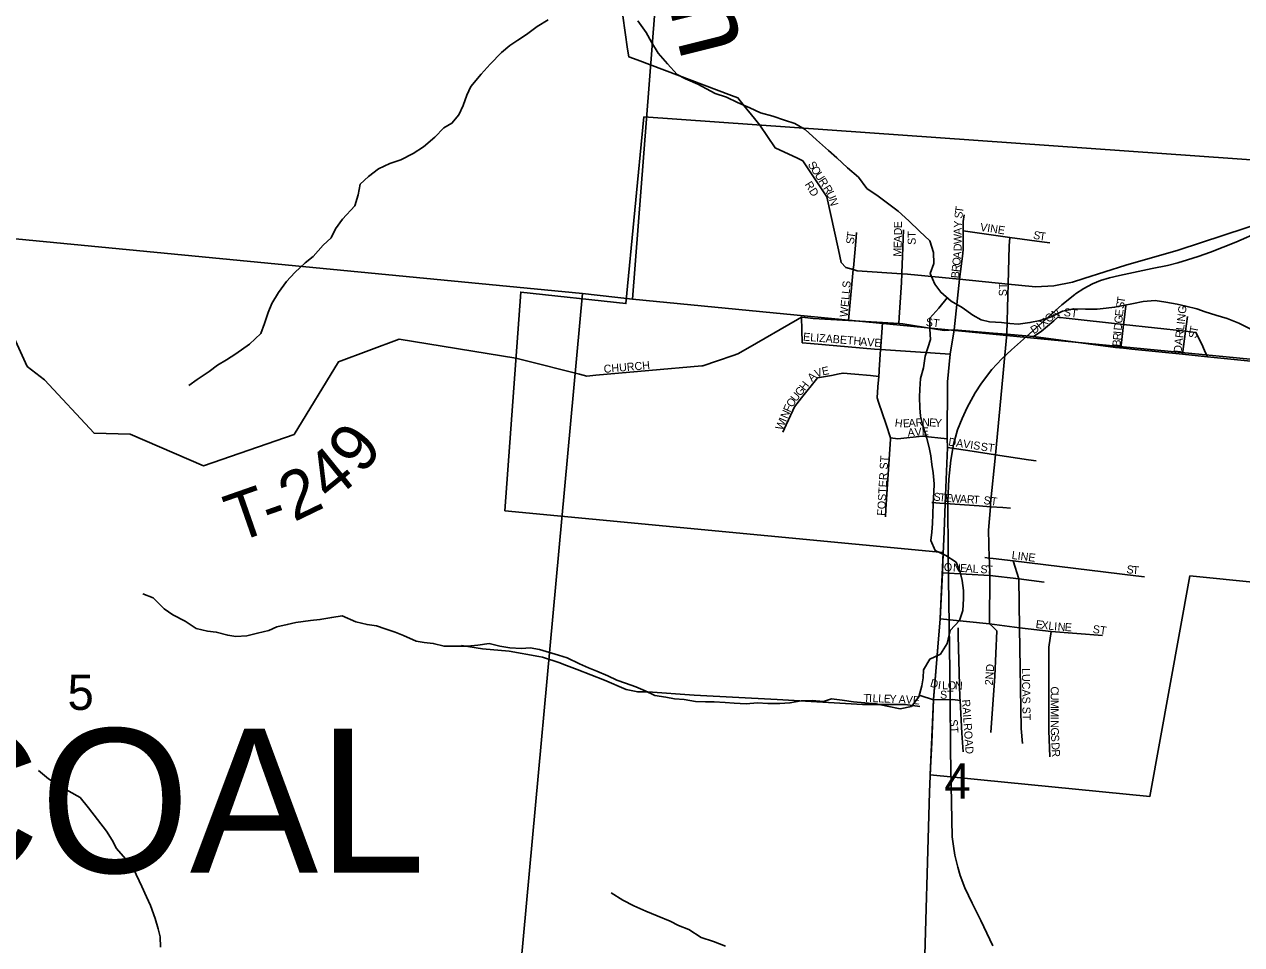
# Model space of a CAD drawing. Extents: x 1715311 to 2083412, y 146837 to 553079.
# Drawn here: x 1931050 to 1938656, y 401506 to 407256 of the extents above; entities that cross this region are included whole.
import ezdxf

# ---------------------------------------------------------------- set-up
doc = ezdxf.new("R2010")
doc.units = 0
for name, color, linetype in [('GM_X_City_Street', 7, 'Continuous'), ('GM_X_City_Street_Text', 7, 'Continuous'), ('GM_X_Corporation', 7, 'Continuous'), ('GM_X_County_Road', 7, 'Continuous'), ('GM_X_Minor_River', 7, 'Continuous'), ('GM_X_Minor_River_Text', 7, 'Continuous'), ('GM_X_Rail_Line', 7, 'Continuous'), ('GM_X_Section', 7, 'Continuous'), ('GM_X_Section_Text', 7, 'Continuous'), ('GM_X_State_Route', 7, 'Continuous'), ('GM_X_Township_Road', 7, 'Continuous'), ('GM_X_Township_Road_Text', 7, 'Continuous'), ('GM_X_Township_ROW', 7, 'Continuous'), ('GM_X_Township_Text', 7, 'Continuous')]:
    doc.layers.add(name, color=color, linetype=linetype)

msp = doc.modelspace()

# ---------------------------------------------------------------- linework, layer by layer
at = {"layer": 'GM_X_City_Street'}
for points in [[(1935880.6, 406419.3), (1935913.9, 406403.7), (1935963.9, 406329.1), (1936064.7, 406177.8), (1936138.1, 405847), (1936154.4, 405768.9), (1936183, 405736.4), (1936229.1, 405723.8), (1936253.3, 405717.1), (1936533.2, 405698), (1936567.8, 405695.6), (1936892.9, 405663.9)], [(1936913.6, 405823.7), (1936917.2, 405851.3), (1936917.1, 405965.8), (1936917, 406024.3), (1936922, 406065)], [(1936230.1, 405735.1), (1936245.4, 405898.8), (1936250.6, 405954.8)], [(1936533.5, 405706), (1936535.2, 405753.3), (1936541.2, 405918), (1936543.2, 405972.8)], [(1936917.1, 405965.8), (1936959.7, 405959.9), (1937208.5, 405925.2), (1937407.4, 405897.5), (1937457.1, 405890.6)], [(1937196.1, 405561.4), (1937197.9, 405632.9), (1937204, 405873.2), (1937208.5, 405925.2)], [(1936892.9, 405663.9), (1936913.6, 405823.7)], [(1936199.4, 405405.5), (1936203.7, 405451.5), (1936229.1, 405723.8), (1936229.8, 405731.1), (1936230.1, 405735.1)], [(1936514.1, 405386.3), (1936516.5, 405424.3), (1936530, 405643.6), (1936533.2, 405698), (1936533.5, 405706)], [(1937173.5, 405146.2), (1937190.1, 405319.9), (1937196.1, 405561.4)], [(1937919.6, 405392.4), (1937925.8, 405444.9), (1937932.1, 405497.7)], [(1934122.1, 405171.2), (1934171.8, 405158.6), (1934519.6, 405070.5), (1934565, 405058.9), (1934620.4, 405063.8), (1935284.3, 405122.6), (1935290.5, 405123), (1935381.6, 405153.9), (1935478.7, 405186.9), (1935509, 405197.2), (1935570.1, 405232.4), (1935881.1, 405411.4), (1935905.8, 405425.7), (1935926.9, 405423.7), (1935929.5, 405423.5)], [(1935911.2, 405267.1), (1935908.5, 405346.4), (1935905.8, 405425.7)], [(1935929.5, 405423.5), (1935979.5, 405418.9), (1936199.4, 405405.5), (1936412.4, 405392.5), (1936514.1, 405386.3), (1936539.9, 405384.7), (1936796.9, 405343.6)], [(1937354.8, 405305.8), (1937404, 405336.8), (1937483.4, 405403.8), (1937507.2, 405425.6), (1937516, 405424.6), (1937525.1, 405423.7)], [(1937525.1, 405423.7), (1937560.1, 405419.8), (1937918.2, 405380.8), (1938305.1, 405338.7), (1938368, 405331.8), (1938371.1, 405331.4), (1938406.6, 405257), (1938425, 405218.4), (1938443.5, 405179.6)], [(1938286.9, 405195.4), (1938292.9, 405242.6), (1938305.1, 405338.7), (1938311, 405384.4), (1938317, 405431.6)], [(1936401.9, 405245.3), (1936408, 405330.4), (1936412.4, 405392.5)], [(1936796.9, 405343.6), (1936797.7, 405343.4), (1936860.8, 405348.1), (1937103.5, 405327.3)], [(1937103.5, 405327.3), (1937190.1, 405319.9), (1937307.9, 405309.9)], [(1937900.8, 405234.3), (1937907, 405286.4), (1937918.2, 405380.8), (1937919.5, 405392.1), (1937919.6, 405392.4)], [(1935911.2, 405267.1), (1935961.4, 405262.7), (1936362.8, 405227.5), (1936400, 405224.9)], [(1937307.9, 405309.9), (1937354.8, 405305.8), (1937867.5, 405237.7), (1937892.1, 405235.2), (1937900.8, 405234.3), (1937969.4, 405227.4), (1938286.9, 405195.4), (1938443.5, 405179.6), (1938734.5, 405150.2), (1938786, 405145)], [(1936391.4, 405098.1), (1936400.4, 405224.8), (1936401, 405233.4), (1936401.9, 405245.3)], [(1936400, 405224.9), (1936400.4, 405224.8), (1936617.5, 405209.7), (1936835.1, 405195.6)], [(1936430.9, 404179), (1936434.1, 404227.5), (1936462.5, 404664.3), (1936463, 404672), (1936434.5, 404756.9), (1936388, 404895.2), (1936378.8, 404922.6), (1936383.7, 404990.8), (1936388.4, 405056.7), (1936390.6, 405087.8), (1936391.4, 405098.1)], [(1937080.4, 403902.7), (1937079.8, 403921.1), (1937073.8, 404096.6), (1937086.1, 404242.1), (1937087.9, 404263.4), (1937117.4, 404567.1), (1937164.8, 405053.9), (1937173.5, 405146.2)], [(1935789.6, 404708.1), (1935810, 404753), (1935851, 404842.8), (1935861.7, 404866.5), (1935907.2, 404923.2), (1935999.6, 405038.9), (1936006, 405046.9), (1936092.9, 405063.1), (1936141.4, 405072.3), (1936166.4, 405076.9), (1936239.4, 405070.3), (1936337.7, 405061.3), (1936388.4, 405056.7)], [(1936463, 404672), (1936509, 404667.4), (1936659.6, 404683), (1936815.8, 404667.2)], [(1936817.6, 404612.8), (1936972, 404589.9), (1937117.4, 404567.1), (1937324, 404534.6), (1937373, 404529.7)], [(1936721.3, 404268.1), (1936770.4, 404264.5), (1936803.6, 404262.2), (1937016, 404247.1), (1937016.1, 404247.1)], [(1937016.1, 404247.1), (1937086.1, 404242.1), (1937163.4, 404236.6), (1937212.6, 404233)], [(1937050.9, 403924.6), (1937079.8, 403921.1), (1937103.4, 403918.2), (1937227.8, 403903.2), (1937995.8, 403810.5), (1938048.4, 403804.1)], [(1937099, 403494), (1937081.5, 403510.7), (1937083.5, 403812.8), (1937080.4, 403902.7)], [(1937286.4, 402763.3), (1937278.2, 402857), (1937267.8, 403485.2), (1937263.9, 403791.3), (1937227.8, 403903.2)], [(1936787.3, 403828.5), (1937083.5, 403812.8), (1937263.9, 403791.3), (1937422.8, 403771.6)], [(1936771.7, 403542.1), (1937081.5, 403510.7), (1937267.8, 403485.2), (1937465.9, 403461.7), (1937787.5, 403438.1)], [(1936896.5, 403049.9), (1936884.8, 403436.3), (1936885.9, 403486.3)], [(1937089.6, 402830.8), (1937114.9, 403183.1), (1937126.6, 403467.6), (1937099, 403494)], [(1937457.1, 402679.3), (1937451.6, 402844.6), (1937451, 403364.8), (1937465.9, 403461.7)], [(1936648.3, 403062.9), (1936730.6, 403036.1), (1936852, 403037.9), (1936897, 403031.3)], [(1936915.3, 402710.8), (1936908.8, 402826.6), (1936897, 403031.3), (1936896.5, 403049.9)], [(1936288.1, 403007.6), (1936553, 403005.8), (1936644.7, 402993.6)]]:
    msp.add_lwpolyline(points, dxfattribs=at)
at = {"layer": 'GM_X_Corporation'}
msp.add_lwpolyline([(1934052.8, 404217.1), (1934152, 405583.3), (1934809.5, 405511.7), (1934921.5, 406677.6), (1939775.2, 406333.8), (1939659.7, 403677.7), (1938332.9, 403810.3), (1938081.7, 402431.6), (1936711.1, 402567.7), (1936730.7, 403037), (1936771.6, 403542.1), (1936791.1, 403956.6)], close=True, dxfattribs=at)
at = {"layer": 'GM_X_County_Road'}
msp.add_lwpolyline([(1934789.6, 407309.3), (1934819.9, 407101.9), (1934827, 407053.6), (1934879.4, 407033.9), (1935467.8, 406812.4), (1935509, 406796.9), (1935546.9, 406749.4), (1935612.3, 406667.5), (1935645.3, 406626.3), (1935741.2, 406484.3), (1935880.6, 406419.3)], dxfattribs=at)
at = {"layer": 'GM_X_Minor_River'}
for points in [[(1934324.1, 407284.8), (1934254, 407243), (1934187.9, 407193.2), (1934133.8, 407157.3), (1934083.8, 407123.5), (1934031.7, 407079.6), (1933961.5, 407007.7), (1933905.3, 406945.8), (1933841.1, 406868), (1933814.9, 406814), (1933792.7, 406748), (1933764.6, 406690), (1933722.4, 406638.1), (1933672.4, 406610.2), (1933614.2, 406550.4), (1933544.1, 406490.5), (1933480, 406448.7), (1933401.9, 406408.9), (1933333.9, 406387.1), (1933263.8, 406353.3), (1933199.7, 406305.5), (1933149.6, 406257.6), (1933135.4, 406191.6), (1933115.2, 406121.5), (1933039.2, 406039.4)], [(1934883.6, 407278.9), (1934935.3, 407204.7), (1934969.1, 407144.5), (1935010.8, 407076.3), (1935068.5, 407010), (1935130.2, 406941.7), (1935182.1, 406915.5), (1935257.9, 406883.2), (1935311.8, 406853), (1935367.6, 406824.8), (1935437.5, 406800.5), (1935507.3, 406768.2), (1935583.1, 406733.9), (1935651, 406703.7), (1935726.8, 406681.4), (1935800.7, 406657.1), (1935864.5, 406636.9), (1935928.4, 406598.6), (1936000.1, 406534.3), (1936075.8, 406468), (1936127.6, 406421.7), (1936193.3, 406359.4), (1936263, 406301.1), (1936314.8, 406230.9), (1936384.5, 406182.6), (1936444.3, 406138.3), (1936510.1, 406088.1), (1936577.8, 406027.8), (1936643.5, 405963.5), (1936707.3, 405903.2), (1936731, 405831), (1936732.8, 405762.9), (1936710.6, 405698.9), (1936738.3, 405632.8), (1936776.1, 405582.6), (1936841.9, 405526.3), (1936909.7, 405488), (1936977.5, 405439.7), (1937029.3, 405409.5), (1937081.2, 405397.3), (1937155.1, 405393.1), (1937207.1, 405386.9), (1937261, 405382.7), (1937333, 405392.5), (1937397, 405406.3), (1937467, 405428), (1937537.1, 405463.9), (1937605.1, 405479.6), (1937681, 405477.4), (1937752.9, 405477.1), (1937808.9, 405483), (1937862.9, 405488.8), (1937916.8, 405498.6), (1937980.8, 405512.4), (1938040.8, 405524.2), (1938116.8, 405530), (1938182.7, 405519.7), (1938252.6, 405507.5), (1938308.5, 405495.3), (1938376.4, 405479), (1938428.3, 405460.8), (1938494.1, 405438.6)], [(1933039.2, 406039.4), (1932993.5, 405979.5), (1932967.1, 405921.6), (1932916.9, 405875.9), (1932854.5, 405806.2), (1932804.3, 405766.5), (1932739.9, 405704.9), (1932687.6, 405649.2), (1932639.2, 405581.4), (1932596.7, 405511.6), (1932574.4, 405455.7), (1932551.9, 405387.7), (1932527.5, 405323.8), (1932457.1, 405258.2), (1932370.8, 405196.7), (1932312.6, 405161), (1932256.5, 405127.4), (1932204.2, 405087.7), (1932130, 405036.1), (1932077.8, 405000.4)], [(1936816.1, 405548.3), (1936763.8, 405482.5), (1936707.6, 405420.6), (1936707.4, 405352.5), (1936711.2, 405286.4), (1936678.8, 405182.4), (1936668.6, 405110.4), (1936650.4, 405042.4), (1936646.2, 404976.3), (1936644, 404926.2), (1936645.8, 404860.1), (1936649.6, 404808.1), (1936663.4, 404750), (1936687.1, 404677.8), (1936702.9, 404611.7), (1936714.7, 404559.6), (1936720.5, 404505.5), (1936728.3, 404453.4), (1936736.1, 404385.3), (1936733.9, 404333.2), (1936729.6, 404263.2), (1936727.4, 404195.1), (1936725.2, 404137), (1936721, 404083), (1936714.9, 404031), (1936740.6, 403968.8), (1936808.4, 403936.5), (1936872.3, 403896.3), (1936898, 403834.1), (1936909.8, 403782), (1936917.6, 403717.9), (1936919.4, 403667.8), (1936915.2, 403593.8), (1936893, 403531.8), (1936834.8, 403467.9), (1936816.6, 403387.8), (1936774.4, 403321.9), (1936708.3, 403290.1), (1936668.1, 403224.2), (1936665.9, 403174.1), (1936657.8, 403124.1), (1936639.6, 403054), (1936593.4, 402994.1), (1936523.4, 402980.4), (1936441.5, 402996.6), (1936373.6, 403010.9), (1936301.7, 403017.1), (1936231.8, 403023.4), (1936159.9, 403033.6), (1936094, 403041.9), (1936044, 403026), (1935972.1, 403032.3), (1935904.1, 403030.5), (1935834.1, 403016.7), (1935770.2, 403012.9), (1935696.2, 403013.2), (1935630.3, 403017.4), (1935560.4, 403011.6), (1935486.4, 403013.9), (1935428.5, 403020.1), (1935360.6, 403022.3), (1935306.6, 403022.5), (1935244.7, 403024.7), (1935172.8, 403037), (1935112.9, 403041.2), (1935058.9, 403051.4), (1934989, 403063.6), (1934929.2, 403091.9), (1934871.3, 403116.1), (1934807.5, 403140.3), (1934751.6, 403158.5), (1934695.7, 403184.8), (1934627.9, 403215), (1934576, 403235.2), (1934520.1, 403261.5), (1934442.3, 403297.8), (1934388.4, 403314), (1934268.6, 403350.4), (1934210.7, 403360.6), (1934156.8, 403356.8), (1934084.8, 403361), (1934020.9, 403371.3), (1933955, 403387.5), (1933883.1, 403377.7), (1933819.1, 403372), (1933745.2, 403370.2), (1933673.2, 403370.4), (1933605.4, 403388.7), (1933549.4, 403394.9), (1933497.5, 403403.1), (1933419.7, 403437.4), (1933367.8, 403457.6), (1933303.9, 403479.8), (1933250, 403498), (1933192.1, 403506.2), (1933122.2, 403522.5), (1933035.7, 403560.3)], [(1938494.1, 405438.6), (1938566, 405418.3), (1938637.8, 405390.1), (1938713.6, 405351.8)], [(1933035.7, 403560.3), (1932971, 403550.6), (1932897, 403537.1), (1932839, 403531.5), (1932747, 403518.1), (1932693, 403506.4), (1932628.9, 403492.8), (1932578.8, 403469.1), (1932506.8, 403451.6), (1932440.7, 403436), (1932372.8, 403430.5), (1932320.9, 403438.8), (1932249.1, 403459.3), (1932195.2, 403465.7), (1932123.4, 403482.2), (1932055.8, 403526.7), (1931978.1, 403567.3), (1931924.4, 403603.7), (1931855, 403672.2), (1931791.2, 403698.7)], [(1931902, 401491.2), (1931898.5, 401555.3), (1931886.8, 401605.4), (1931867.3, 401669.6), (1931837.9, 401749.9), (1931814.3, 401804.1), (1931784.7, 401870.4), (1931731.5, 401978.9), (1931682, 402043.3), (1931626.5, 402107.8), (1931598.9, 402158), (1931563.3, 402214.3), (1931507.9, 402288.8), (1931450.4, 402361.3), (1931398.9, 402425.7), (1931329.3, 402464.2), (1931277.5, 402492.6), (1931201.9, 402541.2), (1931138.3, 402593.6)], [(1935431.3, 401496.3), (1935355.4, 401526.6), (1935279.6, 401550.9), (1935201.8, 401601.2), (1935138, 401625.4), (1935086.1, 401653.6), (1935004.3, 401686), (1934932.5, 401716.2), (1934858.6, 401748.5), (1934788.8, 401784.8), (1934717, 401829.1)]]:
    msp.add_lwpolyline(points, dxfattribs=at)
at = {"layer": 'GM_X_Rail_Line'}
for points in [[(1937619.1, 405571.6), (1937670.5, 405606.7), (1937723.9, 405635.6), (1937773.8, 405656), (1937831.5, 405672.1), (1937892.6, 405686.9), (1938096.5, 405729.8), (1938193.6, 405750.2), (1938256.8, 405766.3), (1938318, 405785.3), (1938384.1, 405805), (1938462.1, 405833.1), (1938620.3, 405895.7), (1938771.5, 405961.8)], [(1937101.1, 401499.5), (1937027.3, 401657.6), (1936971.6, 401765.9), (1936926.6, 401861.5), (1936897.1, 401938.8), (1936883, 401989.4), (1936864.7, 402064.7), (1936854.9, 402121.6), (1936848.6, 402180.7), (1936838, 402715), (1936834.5, 403068.7), (1936826.1, 403650.1), (1936821.9, 403932), (1936819.8, 404280.7), (1936826.1, 404415), (1936838.7, 404533.2), (1936854.9, 404630.2), (1936881.6, 404722.3), (1936909.7, 404793.3), (1936940.7, 404862.2), (1936990.6, 404952.9), (1937031.4, 405014.8), (1937096.1, 405099.1), (1937158.3, 405165.3), (1937219.1, 405221.5), (1937311.9, 405305.8), (1937467.3, 405444.3), (1937532, 405502.7), (1937614, 405567.6)], [(1937614, 405567.6), (1937619.1, 405571.6)]]:
    msp.add_lwpolyline(points, dxfattribs=at)
at = {"layer": 'GM_X_Section'}
for points in [[(1929216.1, 411031.3), (1935235.3, 410505), (1934851, 405539.9), (1934537, 405574.1), (1928680.9, 406138.8)], [(1935235.3, 410505), (1939969.8, 410321.7), (1939733.3, 405066.8), (1939653.3, 405072.8), (1934851, 405539.9)], [(1928614.9, 406143), (1928680.9, 406138.8), (1934537, 405574.1), (1934039.3, 400155.9), (1928437.8, 400678.8)], [(1934537, 405574.1), (1934851, 405539.9), (1939653.3, 405072.8), (1939307.7, 399628.4), (1934039.3, 400155.9)]]:
    msp.add_lwpolyline(points, close=True, dxfattribs=at)
at = {"layer": 'GM_X_State_Route'}
for points in [[(1937671.2, 405667.6), (1937932.5, 405752.4), (1938259.4, 405845.4), (1938823.3, 406031.4), (1939126.2, 406217.4), (1939177.3, 406252.2)], [(1936796.7, 404086), (1936803.6, 404262.2), (1936817.6, 404612.8), (1936815.8, 404667.2), (1936819.3, 405021.8), (1936835.1, 405195.6), (1936860.8, 405348.1), (1936892.9, 405663.9)], [(1936892.9, 405663.9), (1937197.9, 405632.9), (1937348.4, 405617.6), (1937369.3, 405615.6), (1937482.1, 405623.3), (1937599.5, 405644.3), (1937671.2, 405667.6)], [(1936719.5, 402769.5), (1936730.6, 403036.1), (1936771.7, 403542.1), (1936787.3, 403828.5), (1936791.3, 403950.1), (1936796.7, 404086)], [(1936713, 402611.4), (1936719.5, 402769.5)], [(1936566.7, 399872.7), (1936573.1, 399947.1), (1936612.6, 400579.5), (1936648.5, 400964), (1936670, 401222.7), (1936706.6, 402458.8), (1936713, 402611.4)]]:
    msp.add_lwpolyline(points, dxfattribs=at)
at = {"layer": 'GM_X_Township_Road'}
for points in [[(1934122.1, 405171.2), (1933393, 405289.9), (1933013, 405146.7), (1932735.5, 404694.2), (1932169.2, 404496.7), (1931712.2, 404695.8), (1931485.7, 404701.1), (1931176.2, 405034.6), (1931068.5, 405118.8), (1930953.3, 405371.2), (1930566.7, 405467.5), (1930126.6, 405017.7), (1929526, 404919), (1929206.8, 405038.3)], [(1934265.8, 403306.7), (1934079.7, 403339.3), (1933913.8, 403354.9), (1933782, 403375.3)], [(1934420.8, 403257.3), (1934420.7, 403257.3), (1934396, 403266.7), (1934287.1, 403303), (1934265.8, 403306.7), (1934265.8, 403306.7)]]:
    msp.add_lwpolyline(points, dxfattribs=at)
at = {"layer": 'GM_X_Township_ROW'}
msp.add_lwpolyline([(1936288.1, 403007.6), (1935754.4, 403038.5), (1935235.9, 403064.4), (1934945.6, 403085.2), (1934883.3, 403085.2), (1934810.8, 403100.8), (1934676, 403157.8), (1934504.9, 403225.2), (1934420.8, 403257.3)], dxfattribs=at)

# ---------------------------------------------------------------- texts
at = {"layer": 'GM_X_City_Street_Text'}
for s, rotation, p in [('S', 302.69748, (1935943.7, 406380.5)), ('O', 302.71206, (1935962.7, 406350.8)), ('U', 302.71423, (1935986.5, 406313.8)), ('RD', 302.01276, (1935924.5, 406256)), ('R', 302.6884, (1936010.3, 406276.8)), ('R', 302.71335, (1936038.8, 406232.4)), ('U', 294.61943, (1936059.3, 406200.7)), ('N', 285.9394, (1936077, 406162.6)), ('T', 82.24467, (1936914.6, 406074.8)), ('E', 89.99561, (1936533.6, 405981.7)), ('Y', 88.42585, (1936907.8, 405984.2)), ('S', 82.5462, (1936910, 406040)), ('VINE', 351.38926, (1937019.6, 405966.6)), ('T', 81.16658, (1936237.3, 405915.6)), ('A', 88.70919, (1936532.6, 405892.5)), ('D', 89.94783, (1936533.6, 405937.7)), ('ST', 90, (1936619.6, 405878.2)), ('W', 89.89263, (1936907.6, 405883.3)), ('A', 89.91374, (1936907.7, 405940.6)), ('S', 347.80603, (1937350.5, 405918.1)), ('T', 352.66583, (1937389.5, 405909.8)), ('S', 85.132, (1936234.4, 405881.4)), ('E', 87.84476, (1936531.2, 405856.5)), ('D', 87.97743, (1936906, 405837.5)), ('M', 87.8317, (1936529.2, 405803.7)), ('O', 84.59385, (1936897.5, 405746.7)), ('A', 84.60876, (1936901.7, 405790.5)), ('B', 84.6011, (1936890.1, 405667.9)), ('R', 84.60176, (1936893.8, 405707.3)), ('WELLS', 85.0284, (1936194.8, 405425.8)), ('ST', 90, (1937189.2, 405557)), ('T', 81.27876, (1937925, 405511.4)), ('N', 25.31395, (1937482.6, 405415.6)), ('ST', 352.87835, (1937543, 405434.3)), ('S', 81.33277, (1937919.7, 405476.6)), ('DARLING', 83.75787, (1938280.5, 405201.8)), ('ST', 352.87835, (1936680.6, 405372.7)), ('X', 39.82223, (1937417.7, 405359.6)), ('O', 41.22548, (1937452.5, 405388.6)), ('G', 85.10461, (1937910.1, 405385.6)), ('E', 83.29175, (1937913.8, 405429.1)), ('ELIZABETH', 355.48564, (1935914.6, 405280.3)), ('D', 32.07721, (1937356.8, 405318.8)), ('I', 36.68976, (1937397.7, 405344.6)), ('R', 85.08915, (1937901, 405280.4)), ('I', 85.09209, (1937904.4, 405319.9)), ('D', 85.09841, (1937906.3, 405341.8)), ('S', 81.97033, (1938374.6, 405292.1)), ('T', 79.27961, (1938379.4, 405326.3)), ('AVE', 356.0574, (1936270.9, 405249.5)), ('B', 85.11334, (1937897.7, 405240.9)), ('CHURCH', 4.92827, (1934672.2, 405077.9)), ('V', 19.12606, (1935998.8, 405048.4)), ('E', 11.77609, (1936038.7, 405062.4)), ('H', 51.36194, (1935926.9, 404963.6)), ('A', 43.71735, (1935971.8, 405020.9)), ('U', 51.58253, (1935872.1, 404894.8)), ('G', 51.35043, (1935899.4, 404929.2)), ('F', 65.81834, (1935835.1, 404828.8)), ('O', 56.43725, (1935848.4, 404859)), ('W', 66.66232, (1935786.4, 404715.8)), ('I', 66.69021, (1935809, 404768.4)), ('N', 66.67225, (1935817.7, 404788.6)), ('R', 4.13234, (1936620.6, 404742.7)), ('N', 359.25679, (1936658.9, 404745.5)), ('E', 356.20046, (1936702.2, 404745)), ('H', 352.19447, (1936486.6, 404743.3)), ('E', 4.11834, (1936541.5, 404737)), ('A', 5.36263, (1936571, 404679.8)), ('A', 4.14525, (1936576.7, 404739.5)), ('V', 4.35345, (1936614.6, 404683.9)), ('E', 1.69432, (1936657.8, 404687.2)), ('Y', 356.17284, (1936737.3, 404742.6)), ('DAVIS', 351.87427, (1936821.6, 404624.7)), ('ST', 352.87835, (1937023.8, 404593.9)), ('FOSTER ST', 86.7772, (1936428, 404184.7)), ('S', 353.37317, (1936728.9, 404281.5)), ('T', 353.79016, (1936764.3, 404277.4)), ('E', 355.75955, (1936801.2, 404273.4)), ('W', 356.53242, (1936837, 404270.8)), ('A', 356.55894, (1936894.1, 404267.3)), ('R', 356.58166, (1936938, 404264.7)), ('T', 356.55491, (1936977.6, 404262.3)), ('ST', 352.87835, (1937041.4, 404259.5)), ('LINE', 352.87919, (1937217.4, 403916.3)), ('O', 356.56681, (1936794.4, 403841.6)), ('N', 356.56681, (1936851.5, 403838.1)), ('E', 356.55491, (1936895.5, 403835.5)), ('A', 356.56986, (1936930.6, 403833.4)), ('L', 356.55491, (1936974.5, 403830.8)), ('S', 356.55491, (1937022.8, 403827.8)), ('T', 357.46599, (1937058.8, 403825.7)), ('S', 352.16348, (1937934.8, 403828.3)), ('T', 354.14844, (1937971.6, 403823.2)), ('E', 352.63101, (1937367, 403485.1)), ('X', 352.61476, (1937402, 403480.6)), ('L', 354.00155, (1937446.9, 403474.8)), ('I', 355.66857, (1937483.5, 403470.9)), ('N', 355.88397, (1937505.6, 403469.3)), ('E', 355.93825, (1937549.5, 403466.1)), ('ST', 352.40918, (1937723.5, 403454.3)), ('2ND', 85.91715, (1937101.3, 403124.6)), ('LUCAS ST', 270.88095, (1937282.8, 403233.9)), ('D', 343.4871, (1936705.9, 403119.7)), ('I', 351.76538, (1936755.8, 403105.5)), ('L', 359.92078, (1936785.3, 403101.8)), ('O', 359.34422, (1936820.4, 403101.7)), ('N', 356.89533, (1936863.8, 403101.3)), ('T', 358.0326, (1936292.5, 403023.2)), ('I', 358.0326, (1936327.7, 403022)), ('L', 358.05757, (1936349.7, 403021.2)), ('L', 358.0326, (1936384.9, 403020)), ('E', 358.0326, (1936420.1, 403018.8)), ('Y', 358.0326, (1936455.3, 403017.6)), ('A', 357.42026, (1936512.3, 403015.6)), ('V', 355.27267, (1936555.8, 403013.7)), ('E', 354.8031, (1936599.5, 403010.1)), ('ST', 0.00001, (1936771.8, 403042.8)), ('C', 270.0243, (1937463.2, 403119.3)), ('U', 270, (1937463.3, 403079.8)), ('RAILROAD', 273.97322, (1936908.8, 403036.4)), ('M', 270.01141, (1937463.3, 403035.8)), ('M', 270.01822, (1937463.3, 402983)), ('ST', 273.57379, (1936831.8, 402912.2)), ('I', 270, (1937463.3, 402930.2)), ('N', 270.03787, (1937463.3, 402908.1)), ('G', 271.90891, (1937463.4, 402862.3)), ('S', 273.04172, (1937464.9, 402817.3)), ('D', 273.08286, (1937467.5, 402768.9)), ('R', 273.09293, (1937469.8, 402724.9))]:
    msp.add_text(s, height=50, rotation=rotation, dxfattribs=at).set_placement(p)
at = {"layer": 'GM_X_Minor_River_Text'}
msp.add_text('Pigeon', height=500.06, rotation=283.99813, dxfattribs=at).set_placement((1934660.4, 409038.2))
at = {"layer": 'GM_X_Section_Text'}
for s, p in [('5', (1931320.2, 402972.8)), ('4', (1936798.2, 402417.3))]:
    msp.add_text(s, height=221, rotation=0.00001, dxfattribs=at).set_placement(p)
at = {"layer": 'GM_X_Township_Road_Text'}
for s, rotation, p in [('9', 52.04637, (1933161.1, 404434.6)), ('4', 38.92032, (1932964.9, 404265.2)), ('2', 25.79426, (1932735.4, 404144.8)), ('T', 19.23123, (1932372.6, 404015.9)), ('-', 19.23123, (1932584.5, 404089.9))]:
    msp.add_text(s, height=300, rotation=rotation, dxfattribs=at).set_placement(p)
at = {"layer": 'GM_X_Township_Text'}
msp.add_text('COAL', height=900, rotation=0.00001, dxfattribs=at).set_placement((1930279, 401955.4))

doc.saveas('drawing.dxf')
